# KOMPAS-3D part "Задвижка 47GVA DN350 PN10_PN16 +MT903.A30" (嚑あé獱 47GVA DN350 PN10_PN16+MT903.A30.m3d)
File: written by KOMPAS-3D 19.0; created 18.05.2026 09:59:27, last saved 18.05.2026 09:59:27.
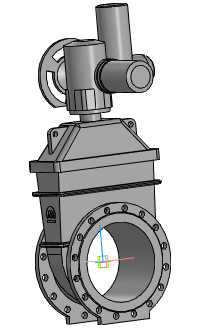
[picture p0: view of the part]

Document properties: Автор: Энергия; Полное имя файла: ..\Задвижка 47GVA DN50_DN1000+MT903.A\Задвижка 47GVA DN350 PN10_PN16+MT903.A30.a3d

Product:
- Part/product: Задвижка 47GVA DN350 PN10_PN16 +MT903.A30
    Масса: 559.603
  - Body: Электропривод МТ903.А30 без блока управления
      Масса: 163.268
  - Body: Задвижка 47GV DN350 PN10_PN16 с маховиком
      Масса: 396.335

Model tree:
1. Операция без истории:1
2. Операция без истории:2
